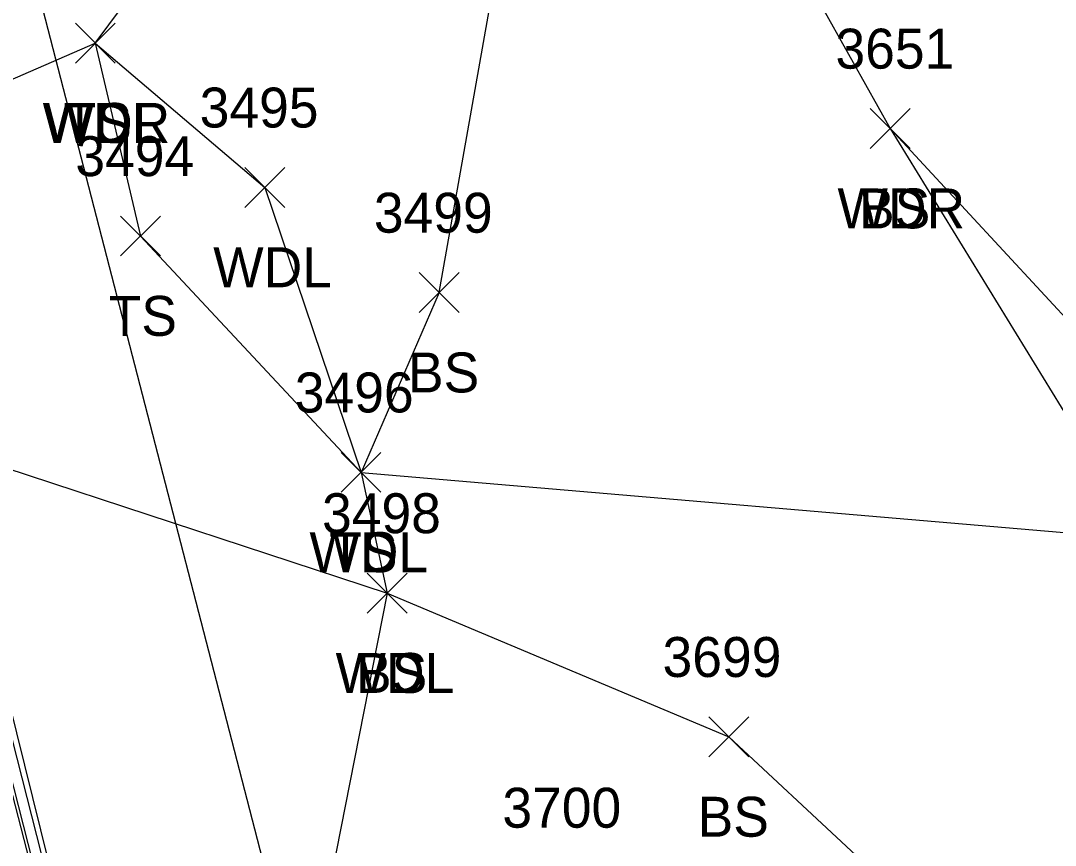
# Model space of a CAD drawing. Extents: x 1601151 to 1602912, y 499508 to 501770.
# Drawn here: x 1601622.4 to 1601674.2, y 500577.9 to 500619.2 of the extents above; entities that cross this region are included whole.
import ezdxf

# ---------------------------------------------------------------- set-up
doc = ezdxf.new("R2010")
doc.units = 0
for name, color, linetype in [('BDC', 7, 'Continuous'), ('BF', 7, 'Continuous'), ('BR', 7, 'Continuous'), ('L_A', 7, 'Continuous'), ('L_I', 7, 'Continuous'), ('L_TIC', 7, 'Continuous'), ('LAWA', 7, 'Continuous'), ('LELB', 7, 'Continuous'), ('UCO', 7, 'Continuous')]:
    doc.layers.add(name, color=color, linetype=linetype)

msp = doc.modelspace()

# ---------------------------------------------------------------- linework, layer by layer
at = {"layer": 'BDC'}
for points in [[(1601627.365, 500562.647), (1601626.817, 500562.743), (1601626.575, 500563.06), (1601618.94, 500592.981), (1601608.354, 500634.47), (1601599.142, 500669.932), (1601586.408, 500719.217), (1601573.699, 500768.593), (1601563.408, 500808.684), (1601554.3, 500843.382), (1601545.843, 500876.671)], [(1601626.62, 500562.484), (1601618.762, 500592.927), (1601608.069, 500634.25), (1601598.914, 500669.817), (1601586.174, 500719.227), (1601573.535, 500768.43), (1601563.157, 500808.618), (1601554.18, 500843.361), (1601545.696, 500876.636)]]:
    msp.add_lwpolyline(points, dxfattribs=at)
at = {"layer": 'BF'}
msp.add_lwpolyline([(1601627.365, 500562.647), (1601619.784, 500593.212)], dxfattribs=at)
at = {"layer": 'BR'}
msp.add_lwpolyline([(1601626.891, 500563.91), (1601619.486, 500592.933), (1601608.823, 500634.178), (1601599.631, 500670.204), (1601586.939, 500719.228), (1601574.289, 500768.594), (1601563.976, 500808.593), (1601554.991, 500843.345), (1601546.615, 500875.695)], dxfattribs=at)
at = {"layer": 'L_TIC'}
for points in [[(1601625.124, 500617.106), (1601627.124, 500619.106)], [(1601627.124, 500617.106), (1601625.124, 500619.106)], [(1601625.124, 500617.106), (1601627.124, 500619.106)], [(1601627.124, 500617.106), (1601625.124, 500619.106)], [(1601625.124, 500617.106), (1601627.124, 500619.106)], [(1601627.124, 500617.106), (1601625.124, 500619.106)], [(1601664.92, 500612.826), (1601666.92, 500614.826)], [(1601666.92, 500612.826), (1601664.92, 500614.826)], [(1601664.92, 500612.826), (1601666.92, 500614.826)], [(1601666.92, 500612.826), (1601664.92, 500614.826)], [(1601633.609, 500609.877), (1601635.609, 500611.877)], [(1601635.609, 500609.877), (1601633.609, 500611.877)], [(1601627.385, 500607.444), (1601629.385, 500609.444)], [(1601629.385, 500607.444), (1601627.385, 500609.444)], [(1601642.337, 500604.61), (1601644.337, 500606.61)], [(1601644.337, 500604.61), (1601642.337, 500606.61)], [(1601638.426, 500595.608), (1601640.426, 500597.608)], [(1601640.426, 500595.608), (1601638.426, 500597.608)], [(1601638.426, 500595.608), (1601640.426, 500597.608)], [(1601640.426, 500595.608), (1601638.426, 500597.608)], [(1601639.736, 500589.561), (1601641.736, 500591.561)], [(1601641.736, 500589.561), (1601639.736, 500591.561)], [(1601639.736, 500589.561), (1601641.736, 500591.561)], [(1601641.736, 500589.561), (1601639.736, 500591.561)], [(1601656.838, 500582.361), (1601658.838, 500584.361)], [(1601658.838, 500582.361), (1601656.838, 500584.361)]]:
    msp.add_lwpolyline(points, dxfattribs=at)
at = {"layer": 'LAWA'}
for points in [[(1601626.124, 500618.106), (1601633.592, 500628.152), (1601648.198, 500633.032), (1601656.043, 500631.466), (1601665.92, 500613.826), (1601678.531, 500593.269), (1601702.446, 500561.858), (1601700.633, 500541.827), (1601700.972, 500520.508), (1601701.434, 500508.423), (1601692.748, 500493.591), (1601673.57, 500488.492), (1601667.988, 500487.133), (1601653.753, 500517.616), (1601642.444, 500550.901)], [(1601626.124, 500618.106), (1601634.609, 500610.877), (1601639.426, 500596.608), (1601640.736, 500590.561)], [(1601640.736, 500590.561), (1601636.552, 500569.306)]]:
    msp.add_lwpolyline(points, dxfattribs=at)
at = {"layer": 'LELB'}
for points in [[(1601643.337, 500605.61), (1601648.198, 500633.032)], [(1601595.511, 500601.966), (1601597.489, 500607.35), (1601613.844, 500605.412), (1601619.332, 500602.406), (1601618.889, 500614.96), (1601626.124, 500618.106), (1601628.385, 500608.444), (1601639.426, 500596.608), (1601678.531, 500593.269), (1601684.776, 500593.468), (1601700.016, 500593.106), (1601710.484, 500590.716), (1601727.344, 500588.151), (1601745.421, 500586.504), (1601758.447, 500586.976)], [(1601665.92, 500613.826), (1601684.776, 500593.468), (1601702.446, 500561.858)], [(1601643.337, 500605.61), (1601639.426, 500596.608)], [(1601616.763, 500598.436), (1601640.736, 500590.561), (1601657.838, 500583.361), (1601670.086, 500571.938), (1601661.389, 500568.714), (1601659.319, 500568.082)]]:
    msp.add_lwpolyline(points, dxfattribs=at)
at = {"layer": 'UCO'}
msp.add_lwpolyline([(1601636.552, 500569.306), (1601558.395, 500871.752)], dxfattribs=at)

# ---------------------------------------------------------------- texts
at = {"layer": 'L_A'}
for s, p in [('WDR', (1601623.486, 500613.106)), ('WDL', (1601623.541, 500613.106)), ('TS', (1601624.533, 500613.106)), ('WDR', (1601663.282, 500608.826)), ('BS', (1601664.361, 500608.826)), ('WDL', (1601632.026, 500605.877)), ('TS', (1601626.794, 500603.444)), ('BS', (1601641.778, 500600.61)), ('WDL', (1601636.844, 500591.608)), ('TS', (1601637.836, 500591.608)), ('WDL', (1601638.153, 500585.561)), ('BS', (1601639.177, 500585.561)), ('BS', (1601656.279, 500578.361))]:
    msp.add_text(s, height=2, dxfattribs=at).set_placement(p)
at = {"layer": 'L_I'}
for s, p in [('3651', (1601663.18, 500616.826)), ('3651', (1601663.18, 500616.826)), ('3495', (1601631.349, 500613.877)), ('3494', (1601625.125, 500611.444)), ('3499', (1601640.07, 500608.61)), ('3496', (1601636.112, 500599.608)), ('3496', (1601636.112, 500599.608)), ('3498', (1601637.476, 500593.561)), ('3498', (1601637.476, 500593.561)), ('3699', (1601654.523, 500586.361)), ('3700', (1601646.505, 500578.812))]:
    msp.add_text(s, height=2, dxfattribs=at).set_placement(p)

doc.saveas('drawing.dxf')
